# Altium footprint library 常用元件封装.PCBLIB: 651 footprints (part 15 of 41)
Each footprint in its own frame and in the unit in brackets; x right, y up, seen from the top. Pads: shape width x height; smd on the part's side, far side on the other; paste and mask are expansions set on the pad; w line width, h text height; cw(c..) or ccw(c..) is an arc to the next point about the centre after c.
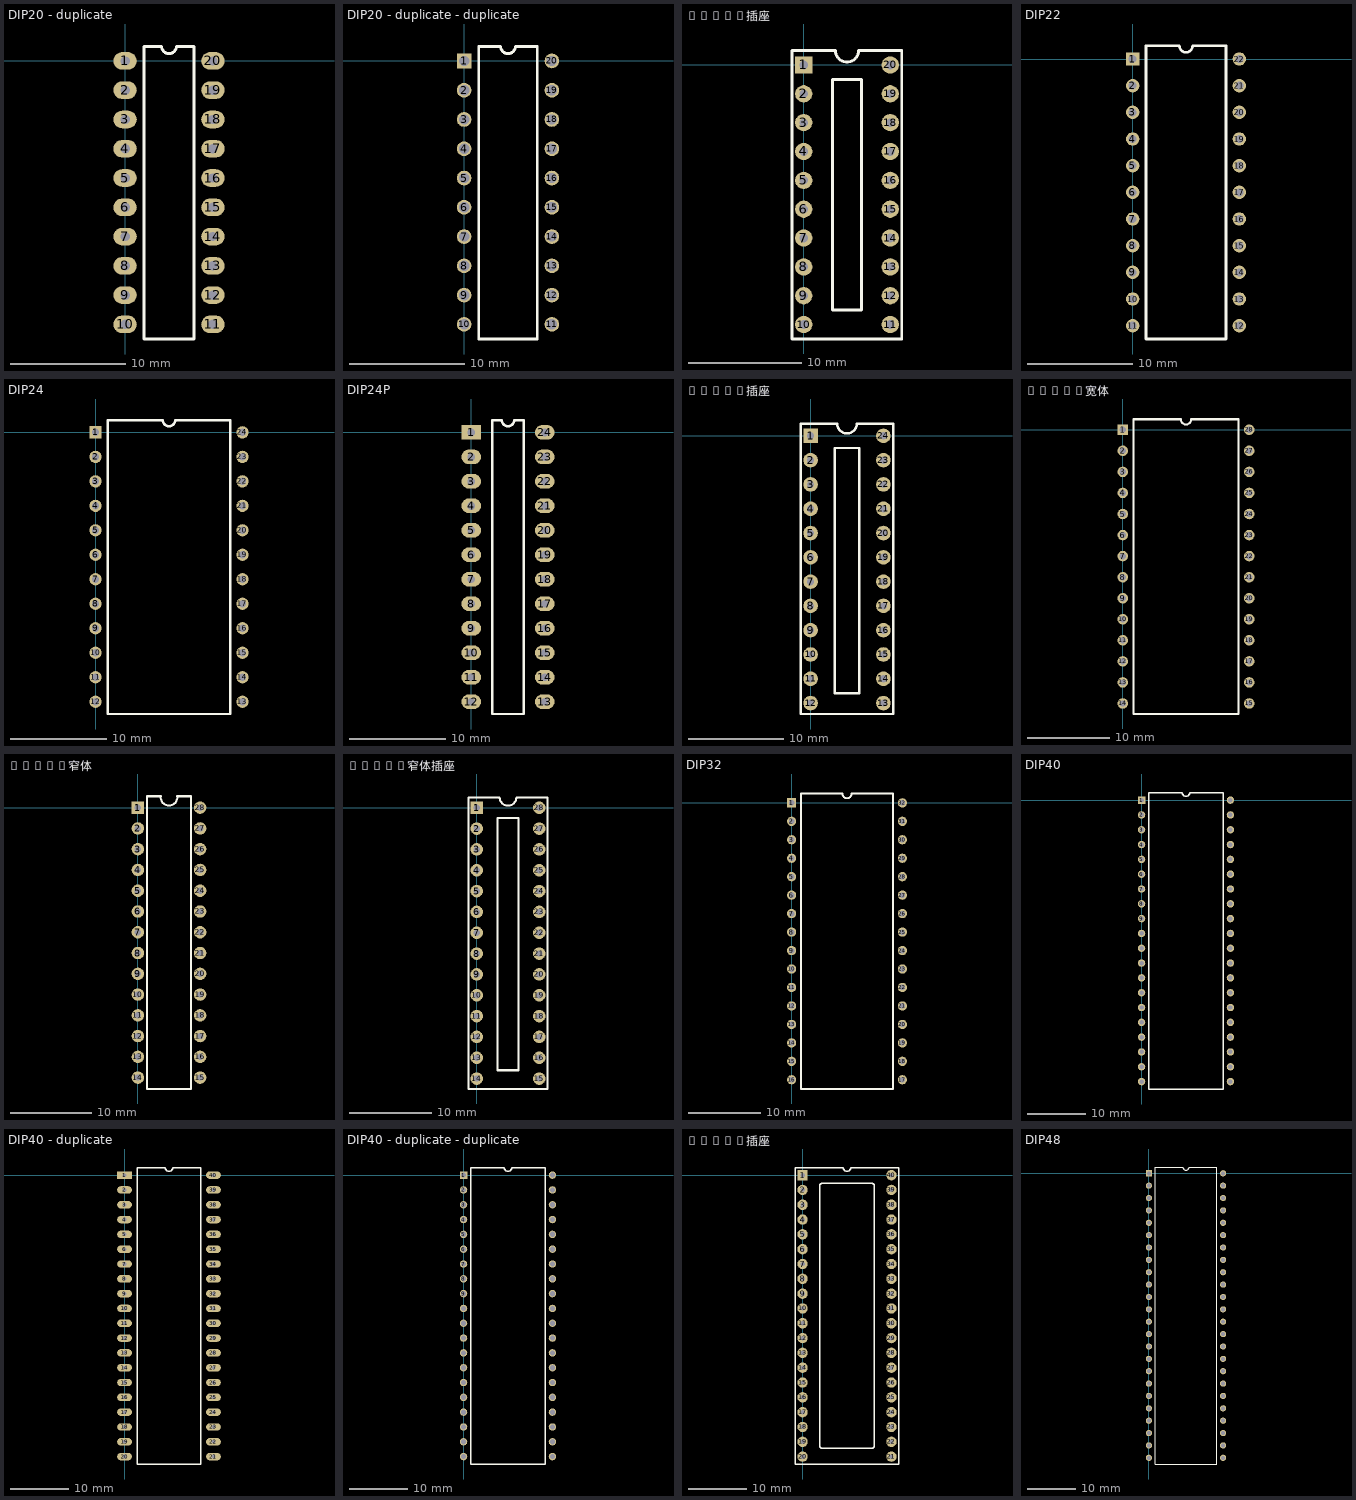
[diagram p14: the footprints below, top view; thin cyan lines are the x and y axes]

## DIP20 - duplicate [mil]
pads (20):
  oval 80x60 hole 32: 1(0,0) 2(0,-100) 3(0,-200) 4(0,-300) 5(0,-400) 6(0,-500) 7(0,-600) 8(0,-700) 9(0,-800) 10(0,-900) 11(300,-900) 12(300,-800) 13(300,-700) 14(300,-600) 15(300,-500) 16(300,-400) 17(300,-300) 18(300,-200) 19(300,-100) 20(300,0)
TopOverlay:
  lines w10: 65,-950 65,50 125,50 ccw(c150,50) 175,50 235,50 235,-950 65,-950

## DIP20 - duplicate - duplicate [mm]
pads (20):
  rect 1.27x1.27 hole 0.9: 1(0,0)
  round 1.27 hole 0.9: 2(0,-2.54) 3(0,-5.08) 4(0,-7.62) 5(0,-10.16) 6(0,-12.7) 7(0,-15.24) 8(0,-17.78) 9(0,-20.32) 10(0,-22.86) 11(7.62,-22.86) 12(7.62,-20.32) 13(7.62,-17.78) 14(7.62,-15.24) 15(7.62,-12.7) 16(7.62,-10.16) 17(7.62,-7.62) 18(7.62,-5.08) 19(7.62,-2.54) 20(7.62,0)
TopOverlay:
  lines w0.254: 1.27,-24.13 1.27,1.27 3.175,1.27 ccw(c3.81,1.27) 4.445,1.27 6.35,1.27 6.35,-24.13 1.27,-24.13

## DIP20插座 [mil]
pads (20):
  rect 60x60 hole 30: 1(0,0)
  round 60 hole 30: 2(0,-100) 3(0,-200) 4(0,-300) 5(0,-400) 6(0,-500) 7(0,-600) 8(0,-700) 9(0,-800) 10(0,-900) 11(300,-900) 12(300,-800) 13(300,-700) 14(300,-600) 15(300,-500) 16(300,-400) 17(300,-300) 18(300,-200) 19(300,-100) 20(300,0)
TopOverlay:
  lines w10: -40,-950 -40,50 110,50 ccw(c150,50) 190,50 340,50 340,-950 -40,-950 ; 100,-850 100,-50 200,-50 200,-850 100,-850

## DIP22 [mil]
pads (22):
  rect 50x50 hole 30: 1(0,0)
  round 50 hole 30: 2(0,-100) 3(0,-200) 4(0,-300) 5(0,-400) 6(0,-500) 7(0,-600) 8(0,-700) 9(0,-800) 10(0,-900) 11(0,-1000) 12(400,-1000) 13(400,-900) 14(400,-800) 15(400,-700) 16(400,-600) 17(400,-500) 18(400,-400) 19(400,-300) 20(400,-200) 21(400,-100) 22(400,0)
TopOverlay:
  lines w10: 50,-1050 50,50 175,50 ccw(c200,50) 225,50 350,50 350,-1050 50,-1050

## DIP24 [mil]
pads (24):
  rect 50x50 hole 30: 1(0,0)
  round 50 hole 30: 2(0,-100) 3(0,-200) 4(0,-300) 5(0,-400) 6(0,-500) 7(0,-600) 8(0,-700) 9(0,-800) 10(0,-900) 11(0,-1000) 12(0,-1100) 13(600,-1100) 14(600,-1000) 15(600,-900) 16(600,-800) 17(600,-700) 18(600,-600) 19(600,-500) 20(600,-400) 21(600,-300) 22(600,-200) 23(600,-100) 24(600,0)
TopOverlay:
  lines w10: 50,-1150 550,-1150 550,50 325,50 cw(c300,50) 275,50 50,50 50,-1150

## DIP24P [mil]
pads (24):
  rect 80x60 hole 32: 1(0,0)
  oval 80x60 hole 32: 2(0,-100) 3(0,-200) 4(0,-300) 5(0,-400) 6(0,-500) 7(0,-600) 8(0,-700) 9(0,-800) 10(0,-900) 11(0,-1000) 12(0,-1100) 13(300,-1100) 14(300,-1000) 15(300,-900) 16(300,-800) 17(300,-700) 18(300,-600) 19(300,-500) 20(300,-400) 21(300,-300) 22(300,-200) 23(300,-100) 24(300,0)
TopOverlay:
  lines w10: 85,-1150 85,50 125,50 ccw(c150,50) 175,50 215,50 215,-1150 85,-1150

## DIP24插座 [mil]
pads (24):
  rect 60x60 hole 30: 1(0,0)
  round 60 hole 30: 2(0,-100) 3(0,-200) 4(0,-300) 5(0,-400) 6(0,-500) 7(0,-600) 8(0,-700) 9(0,-800) 10(0,-900) 11(0,-1000) 12(0,-1100) 13(300,-1100) 14(300,-1000) 15(300,-900) 16(300,-800) 17(300,-700) 18(300,-600) 19(300,-500) 20(300,-400) 21(300,-300) 22(300,-200) 23(300,-100) 24(300,0)
TopOverlay:
  lines w10: -40,-1145 -40,50 110,50 ccw(c150,50) 190,50 340,50 340,-1145 -40,-1145 ; 100,-1060 100,-50 200,-50 200,-1060 100,-1060

## DIP28宽体 [mil]
pads (28):
  rect 50x50 hole 30: 1(0,0)
  round 50 hole 30: 2(0,-100) 3(0,-200) 4(0,-300) 5(0,-400) 6(0,-500) 7(0,-600) 8(0,-700) 9(0,-800) 10(0,-900) 11(0,-1000) 12(0,-1100) 13(0,-1200) 14(0,-1300) 15(600,-1300) 16(600,-1200) 17(600,-1100) 18(600,-1000) 19(600,-900) 20(600,-800) 21(600,-700) 22(600,-600) 23(600,-500) 24(600,-400) 25(600,-300) 26(600,-200) 27(600,-100) 28(600,0)
TopOverlay:
  lines w10: 50,-1350 50,50 275,50 ccw(c300,50) 325,50 550,50 550,-1350 50,-1350

## DIP28窄体 [mil]
pads (28):
  rect 60x60 hole 30: 1(0,0)
  round 60 hole 30: 2(0,-100) 3(0,-200) 4(0,-300) 5(0,-400) 6(0,-500) 7(0,-600) 8(0,-700) 9(0,-800) 10(0,-900) 11(0,-1000) 12(0,-1100) 13(0,-1200) 14(0,-1300) 15(300,-1300) 16(300,-1200) 17(300,-1100) 18(300,-1000) 19(300,-900) 20(300,-800) 21(300,-700) 22(300,-600) 23(300,-500) 24(300,-400) 25(300,-300) 26(300,-200) 27(300,-100) 28(300,0)
TopOverlay:
  lines w10: 45,55 45,-1355 255,-1355 255,55 189.73,55 ; 45.04,54.96 110.31,54.96 ccw(c150,50) 189.69,54.96

## DIP28窄体插座 [mil]
pads (28):
  rect 60x60 hole 30: 1(0,0)
  round 60 hole 30: 2(0,-100) 3(0,-200) 4(0,-300) 5(0,-400) 6(0,-500) 7(0,-600) 8(0,-700) 9(0,-800) 10(0,-900) 11(0,-1000) 12(0,-1100) 13(0,-1200) 14(0,-1300) 15(300,-1300) 16(300,-1200) 17(300,-1100) 18(300,-1000) 19(300,-900) 20(300,-800) 21(300,-700) 22(300,-600) 23(300,-500) 24(300,-400) 25(300,-300) 26(300,-200) 27(300,-100) 28(300,0)
TopOverlay:
  lines w10: -40,-1350 340,-1350 340,50 190,50 cw(c150,50) 110,50 -40,50 -40,-1350 ; 100,-1260 200,-1260 200,-50 100,-50 100,-1260

## DIP32 [mil]
pads (32):
  rect 50x50 hole 30: 1(0,0)
  round 50 hole 30: 2(0,-100) 3(0,-200) 4(0,-300) 5(0,-400) 6(0,-500) 7(0,-600) 8(0,-700) 9(0,-800) 10(0,-900) 11(0,-1000) 12(0,-1100) 13(0,-1200) 14(0,-1300) 15(0,-1400) 16(0,-1500) 17(600,-1500) 18(600,-1400) 19(600,-1300) 20(600,-1200) 21(600,-1100) 22(600,-1000) 23(600,-900) 24(600,-800) 25(600,-700) 26(600,-600) 27(600,-500) 28(600,-400) 29(600,-300) 30(600,-200) 31(600,-100) 32(600,0)
TopOverlay:
  lines w10: 50,-1550 50,50 275,50 ccw(c300,50) 325,50 550,50 550,-1550 50,-1550

## DIP40 [mil]
pads (40):
  rect 50x50 hole 30: 1(0,0)
  round 50 hole 30: 2(0,-100) 3(0,-200) 4(0,-300) 5(0,-400) 6(0,-500) 7(0,-600) 8(0,-700) 9(0,-800) 10(0,-900) 11(0,-1000) 12(0,-1100) 13(0,-1200) 14(0,-1300) 15(0,-1400) 16(0,-1500) 17(0,-1600) 18(0,-1700) 19(0,-1800) 20(0,-1900) 21(600,-1900) 22(600,-1800) 23(600,-1700) 24(600,-1600) 25(600,-1500) 26(600,-1400) 27(600,-1300) 28(600,-1200) 29(600,-1100) 30(600,-1000) 31(600,-900) 32(600,-800) 33(600,-700) 34(600,-600) 35(600,-500) 36(600,-400) 37(600,-300) 38(600,-200) 39(600,-100) 40(600,0)
TopOverlay:
  lines w10: 50,-1950 550,-1950 550,50 325,50 cw(c300,50) 275,50 50,50 50,-1950

## DIP40 - duplicate [mil]
pads (40):
  rect 100x50 hole 25: 1(0,0)
  oval 100x50 hole 25: 2(0,-100) 3(0,-200) 4(0,-300) 5(0,-400) 6(0,-500) 7(0,-600) 8(0,-700) 9(0,-800) 10(0,-900) 11(0,-1000) 12(0,-1100) 13(0,-1200) 14(0,-1300) 15(0,-1400) 16(0,-1500) 17(0,-1600) 18(0,-1700) 19(0,-1800) 20(0,-1900) 21(600,-1900) 22(600,-1800) 23(600,-1700) 24(600,-1600) 25(600,-1500) 26(600,-1400) 27(600,-1300) 28(600,-1200) 29(600,-1100) 30(600,-1000) 31(600,-900) 32(600,-800) 33(600,-700) 34(600,-600) 35(600,-500) 36(600,-400) 37(600,-300) 38(600,-200) 39(600,-100) 40(600,0)
TopOverlay:
  lines w10: 85,-1950 515,-1950 515,50 325,50 cw(c300,50) 275,50 85,50 85,-1950

## DIP40 - duplicate - duplicate [mm]
pads (40):
  rect 1.27x1.27 hole 0.9: 1(0,0)
  round 1.27 hole 0.9: 2(0,-2.54) 3(0,-5.08) 4(0,-7.62) 5(0,-10.16) 6(0,-12.7) 7(0,-15.24) 8(0,-17.78) 9(0,-20.32) 10(0,-22.86) 11(0,-25.4) 12(0,-27.94) 13(0,-30.48) 14(0,-33.02) 15(0,-35.56) 16(0,-38.1) 17(0,-40.64) 18(0,-43.18) 19(0,-45.72) 20(0,-48.26) 21(15.24,-48.26) 22(15.24,-45.72) 23(15.24,-43.18) 24(15.24,-40.64) 25(15.24,-38.1) 26(15.24,-35.56) 27(15.24,-33.02) 28(15.24,-30.48) 29(15.24,-27.94) 30(15.24,-25.4) 31(15.24,-22.86) 32(15.24,-20.32) 33(15.24,-17.78) 34(15.24,-15.24) 35(15.24,-12.7) 36(15.24,-10.16) 37(15.24,-7.62) 38(15.24,-5.08) 39(15.24,-2.54) 40(15.24,0)
TopOverlay:
  lines w0.254: 1.27,-49.53 1.27,1.27 6.985,1.27 ccw(c7.62,1.27) 8.255,1.27 13.97,1.27 13.97,-49.53 1.27,-49.53

## DIP40插座 [mil]
pads (40):
  rect 70x70 hole 30: 1(0,0)
  round 70 hole 30: 2(0,-100) 3(0,-200) 4(0,-300) 5(0,-400) 6(0,-500) 7(0,-600) 8(0,-700) 9(0,-800) 10(0,-900) 11(0,-1000) 12(0,-1100) 13(0,-1200) 14(0,-1300) 15(0,-1400) 16(0,-1500) 17(0,-1600) 18(0,-1700) 19(0,-1800) 20(0,-1900) 21(600,-1900) 22(600,-1800) 23(600,-1700) 24(600,-1600) 25(600,-1500) 26(600,-1400) 27(600,-1300) 28(600,-1200) 29(600,-1100) 30(600,-1000) 31(600,-900) 32(600,-800) 33(600,-700) 34(600,-600) 35(600,-500) 36(600,-400) 37(600,-300) 38(600,-200) 39(600,-100) 40(600,0)
TopOverlay:
  lines w10: -50,-1950 -50,50 275,50 ccw(c300,50) 325,50 650,50 650,-1950 -50,-1950 ; 115,-1825 ccw(c135,-1825) 135,-1845 465,-1845 ccw(c465,-1825) 485,-1825 485,-75 ccw(c465,-75) 465,-55 135,-55 ccw(c135,-75) 115,-75 115,-1825

## DIP48 [mil]
pads (48):
  rect 50x50 hole 32: 1(0,0)
  round 50 hole 32: 2(0,-100) 3(0,-200) 4(0,-300) 5(0,-400) 6(0,-500) 7(0,-600) 8(0,-700) 9(0,-800) 10(0,-900) 11(0,-1000) 12(0,-1100) 13(0,-1200) 14(0,-1300) 15(0,-1400) 16(0,-1500) 17(0,-1600) 18(0,-1700) 19(0,-1800) 20(0,-1900) 21(0,-2000) 22(0,-2100) 23(0,-2200) 24(0,-2300) 25(600,-2300) 26(600,-2200) 27(600,-2100) 28(600,-2000) 29(600,-1900) 30(600,-1800) 31(600,-1700) 32(600,-1600) 33(600,-1500) 34(600,-1400) 35(600,-1300) 36(600,-1200) 37(600,-1100) 38(600,-1000) 39(600,-900) 40(600,-800) 41(600,-700) 42(600,-600) 43(600,-500) 44(600,-400) 45(600,-300) 46(600,-200) 47(600,-100) 48(600,0)
TopOverlay:
  lines w10: 50,-2350 50,50 275,50 ccw(c300,50) 325,50 550,50 550,-2350 50,-2350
